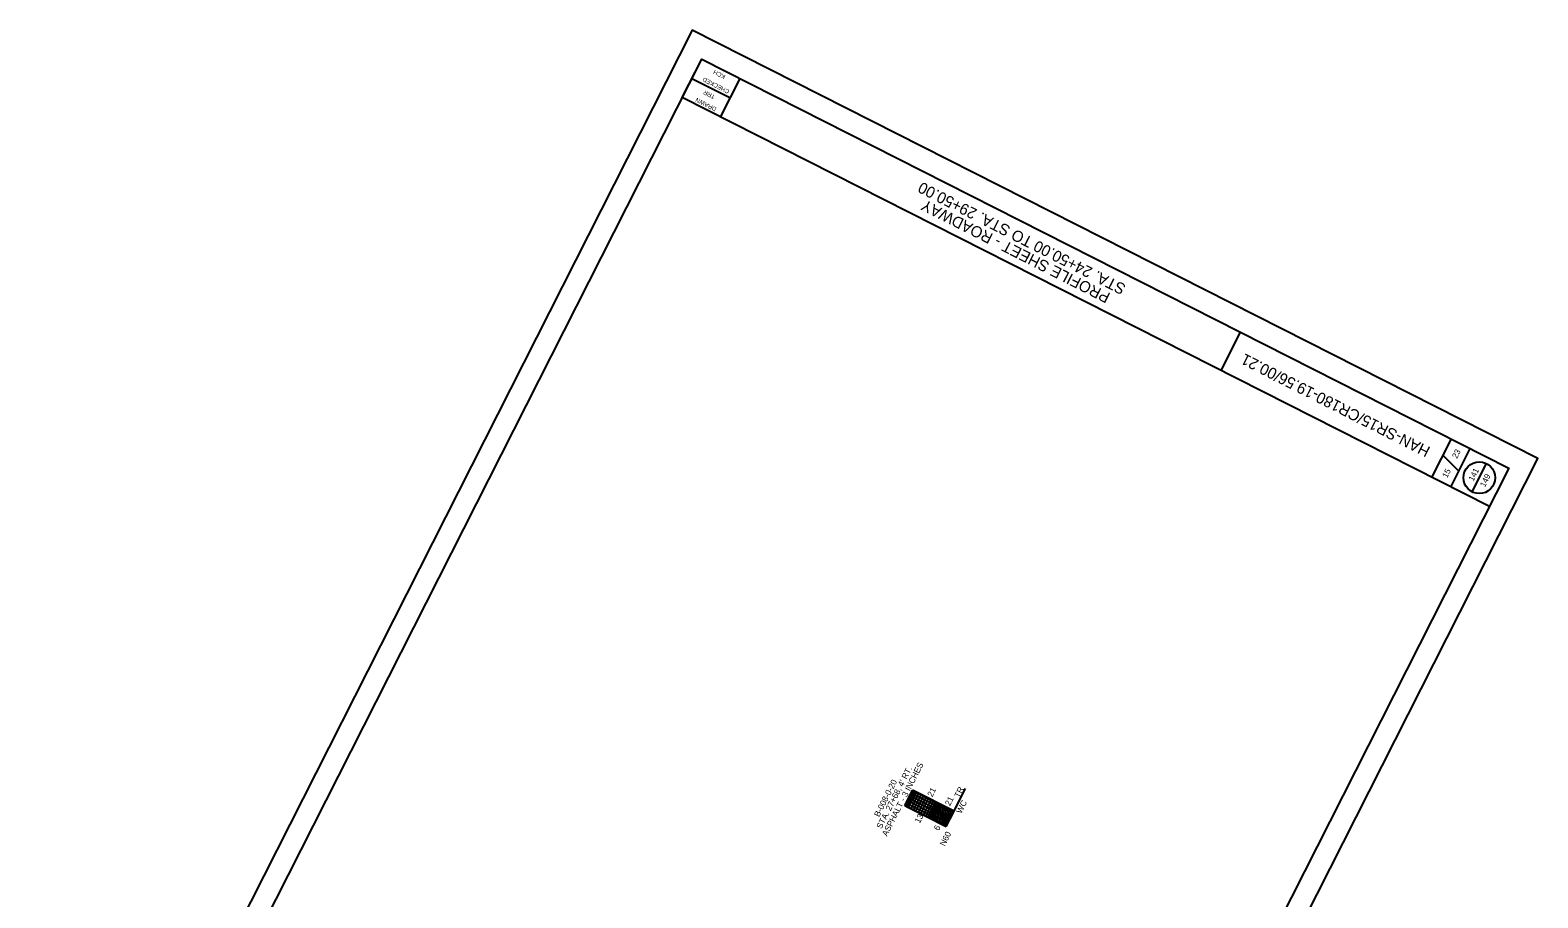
# Model space of a CAD drawing. Extents: x 1526692 to 1527392, y 633743 to 634549.
# Drawn here: x 1526692 to 1527392, y 634146 to 634549 of the extents above; entities that cross this region are included whole.
import ezdxf

# ---------------------------------------------------------------- set-up
doc = ezdxf.new("R2010")
doc.units = 0
for name, color, linetype in [('SC_Scratch6', 7, 'Continuous'), ('SH_Border', 7, 'Continuous'), ('SH_Cut_Line', 7, 'Continuous'), ('SH_Data', 7, 'Continuous')]:
    doc.layers.add(name, color=color, linetype=linetype)

msp = doc.modelspace()

# ---------------------------------------------------------------- linework, layer by layer
at = {"layer": 'SH_Border'}
for p, q in [((1526994.83, 634517.49), (1527003.87, 634535.33)), ((1526999.35, 634526.41), (1527017.19, 634517.38)), ((1527012.67, 634508.45), (1527021.71, 634526.3)), ((1527369.5, 634327.7), (1526994.83, 634517.49)), ((1527244.95, 634390.79), (1527253.99, 634408.63)), ((1527342.78, 634341.17), (1527351.67, 634358.74)), ((1527355.27, 634344.04), (1527347.97, 634351.42)), ((1527351.56, 634336.72), (1527360.46, 634354.29))]:
    msp.add_line(p, q, dxfattribs=at)
msp.add_lwpolyline([(1526719.18, 633973.32), (1527003.87, 634535.33), (1527378.54, 634345.54), (1527093.86, 633783.53)], close=True, dxfattribs=at)
at = {"layer": 'SH_Cut_Line'}
msp.add_lwpolyline([(1527084.7, 633743.33), (1527391.98, 634349.95), (1526999.46, 634548.77), (1526692.19, 633942.16)], close=True, dxfattribs=at)
at = {"layer": 'SH_Data'}
for p, q in [((1527361.46, 634334.47), (1527368.13, 634347.64)), ((1527099.19, 634188.34), (1527102.81, 634195.48)), ((1527099.97, 634192.54), (1527101.74, 634196.02)), ((1527103.52, 634195.12), (1527101.42, 634190.97)), ((1527121.01, 634186.26), (1527101.74, 634196.02)), ((1527119.25, 634182.77), (1527126.32, 634196.73)), ((1527098.12, 634188.88), (1527099.97, 634192.54)), ((1527098.12, 634188.88), (1527099.19, 634188.34)), ((1527099.19, 634188.34), (1527099.9, 634187.98)), ((1527099.9, 634187.98), (1527101.76, 634191.64)), ((1527099.9, 634187.98), (1527108.83, 634183.46)), ((1527110.68, 634187.11), (1527112.44, 634190.59)), ((1527108.83, 634183.46), (1527110.68, 634187.12)), ((1527108.83, 634183.46), (1527117.39, 634179.12)), ((1527117.39, 634179.12), (1527119.25, 634182.78))]:
    msp.add_line(p, q, dxfattribs=at)
for points in [[(1527098.12, 634188.88), (1527101.74, 634196.02)], [(1527099.19, 634188.34), (1527102.81, 634195.48)], [(1527099.91, 634187.98), (1527103.52, 634195.12)], [(1527100.9, 634194.37), (1527102.04, 634194.74), (1527102.51, 634194.9)], [(1527101.43, 634192.75), (1527100.9, 634194.37)], [(1527101.05, 634187.4), (1527104.64, 634194.49)], [(1527101.74, 634196.02), (1527121.01, 634186.26)], [(1527102.36, 634194.58), (1527101.91, 634195.93)], [(1527103.25, 634194.58), (1527102.98, 634195.39)], [(1527112.3, 634190.32), (1527103.38, 634194.84)], [(1527112.42, 634190.54), (1527103.5, 634195.06)], [(1527098.12, 634188.88), (1527098.12, 634188.88), (1527099.73, 634189.41)], [(1527098.12, 634188.88), (1527117.39, 634179.12)], [(1527099.05, 634190.71), (1527100.19, 634191.09), (1527100.66, 634191.24)], [(1527099.58, 634189.1), (1527099.05, 634190.71)], [(1527099.19, 634188.34), (1527099.19, 634188.34), (1527100.27, 634188.69)], [(1527099.9, 634187.98), (1527101.76, 634191.64)], [(1527108.83, 634183.46), (1527099.9, 634187.98)], [(1527099.93, 634192.45), (1527119.2, 634182.69)], [(1527099.97, 634192.54), (1527099.98, 634192.54), (1527101.59, 634193.07)], [(1527099.97, 634192.54), (1527099.97, 634192.54)], [(1527100.5, 634190.93), (1527099.97, 634192.54)], [(1527100.12, 634190.17), (1527100.79, 634190.39), (1527101.19, 634190.52)], [(1527100.47, 634189.09), (1527100.12, 634190.17)], [(1527109.41, 634184.6), (1527100.48, 634189.12)], [(1527101.04, 634192), (1527101.05, 634192), (1527102.12, 634192.35)], [(1527101.04, 634192), (1527101.04, 634192)], [(1527101.4, 634190.92), (1527101.04, 634192)], [(1527109.99, 634185.74), (1527101.06, 634190.26)], [(1527110.57, 634186.89), (1527101.64, 634191.41)], [(1527101.97, 634193.83), (1527102.64, 634194.05), (1527103.05, 634194.18)], [(1527102.32, 634192.75), (1527101.97, 634193.82)], [(1527102.19, 634186.82), (1527105.78, 634193.91)], [(1527111.15, 634188.03), (1527102.22, 634192.55)], [(1527111.72, 634189.17), (1527102.8, 634193.69)], [(1527103.34, 634186.24), (1527106.93, 634193.33)], [(1527104.48, 634185.66), (1527108.07, 634192.75)], [(1527105.62, 634185.08), (1527109.22, 634192.17)], [(1527106.77, 634184.5), (1527110.36, 634191.59)], [(1527107.91, 634183.92), (1527111.5, 634191.01)], [(1527108.83, 634183.46), (1527112.44, 634190.6)], [(1527111.9, 634186.49), (1527111.3, 634188.33)], [(1527113.12, 634185.88), (1527111.92, 634189.55)], [(1527114.34, 634185.26), (1527112.62, 634190.51)], [(1527115.56, 634184.64), (1527113.84, 634189.89)], [(1527116.78, 634184.02), (1527115.06, 634189.27)], [(1527118, 634183.4), (1527116.28, 634188.65)], [(1527119.22, 634182.79), (1527117.5, 634188.04)], [(1527119.85, 634183.97), (1527118.72, 634187.42)], [(1527121.01, 634186.26), (1527123.41, 634191)], [(1527110.05, 634182.84), (1527109.45, 634184.68)], [(1527111.27, 634182.22), (1527110.06, 634185.9)], [(1527112.49, 634181.6), (1527110.68, 634187.12)], [(1527113.71, 634180.98), (1527111.9, 634186.5)], [(1527114.93, 634180.37), (1527113.12, 634185.88)], [(1527116.15, 634179.75), (1527114.34, 634185.26)], [(1527117.37, 634179.13), (1527115.56, 634184.64)], [(1527118, 634180.31), (1527116.78, 634184.03)], [(1527117.39, 634179.12), (1527121.01, 634186.26)], [(1527118.62, 634181.53), (1527118, 634183.41)], [(1527119.24, 634182.75), (1527119.22, 634182.79)], [(1527120.47, 634185.19), (1527119.94, 634186.8)], [(1527121.09, 634186.41), (1527121.08, 634186.45)]]:
    msp.add_lwpolyline(points, dxfattribs=at)
msp.add_circle((1527364.79, 634341.06), 7.38, dxfattribs=at)

# ---------------------------------------------------------------- texts
at = {"layer": 'SC_Scratch6'}
for s, p in [('23', (1527354.44, 634349.72)), ('15', (1527349.87, 634340.69)), ('141', (1527362.07, 634339.15)), ('149', (1527367.38, 634336.47))]:
    msp.add_text(s, height=2.757, rotation=63.13565, dxfattribs=at).set_placement(p)
at = {"layer": 'SH_Data'}
for s, height, rotation, p in [('CHECKED', 2, 153.13565, (1527016.94, 634520.92)), ('KCH', 2, 153.13565, (1527015.09, 634527.79)), ('DRAWN', 2, 153.13565, (1527010.94, 634512.75)), ('TRR', 2, 153.13565, (1527010.29, 634518.46)), ('STA. 24+50.00 TO STA. 29+50.00', 5.1975, 153.13565, (1527201.2, 634430.36)), ('PROFILE SHEET - ROADWAY', 5.1975, 153.13565, (1527193.96, 634426.48)), ('HAN-SR15/CR180-19.56/00.21', 5.1975, 153.13565, (1527342.47, 634355.03)), ('ASPHALT - 3 INCHES', 2.8, 63.13565, (1527089.89, 634174.41)), ("STA. 27+68, 4' RT.", 2.8, 63.13565, (1527087.33, 634177.84)), ('B-008-0-20', 2.8, 63.13565, (1527086.23, 634183.37)), ('21', 2.8, 63.13565, (1527110.91, 634192.66)), ('TR', 2.8, 63.13565, (1527123.47, 634192.25)), ('21', 2.8, 63.13565, (1527119.1, 634188.51)), ('WC', 2.8, 63.13565, (1527124.36, 634184.91)), ('13', 2.8, 63.13565, (1527105.09, 634180.44)), ('6', 2.8, 63.13565, (1527113.93, 634176.99)), ('N60', 2.8, 63.13565, (1527116.7, 634169.8))]:
    msp.add_text(s, height=height, rotation=rotation, dxfattribs=at).set_placement(p)

doc.saveas('drawing.dxf')
